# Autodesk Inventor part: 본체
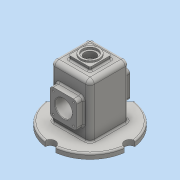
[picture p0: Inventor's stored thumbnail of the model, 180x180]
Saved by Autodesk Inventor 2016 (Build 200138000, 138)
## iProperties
Created: 2018-07
Part Number: 본체
Material: 일반
Document SubType Name: Modeling
Designer: 2-
Density: 1 g/cm^3
Appearance: 기본값
Author: 2-
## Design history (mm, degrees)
sketch "스케치1"
  geometry: C1 r 75 at (0, 0); 1 further point
  constraints: 1 centre point, 1 coincident
  dimensions: "d0" = 150 diameter of C1
extrude "돌출1" new body sketch "스케치1" distance "d1" = 10; taper "d2" = 0 deg
sketch "스케치2"
  geometry: L1 (0, 0)-(75, 0); C1 r 10 at (75, 0); 1 further point
  constraints: 2 end point, 1 centre point, 1 coincident, 1 horizontal, 1 horizontal alignment, 1 other
  dimensions: "d3" = 20 diameter of C1
extrude "돌출2" cut sketch "스케치2" distance "d4" = 10; taper "d5" = 0 deg
sketch "스케치3"
  geometry: L1 (-37, -37)-(37, -37); L2 (37, -37)-(37, 37); L3 (37, 37)-(-37, 37); L4 (-37, 37)-(-37, -37); L5 (-37, -37)-(37, 37); L6 (37, -37)-(-37, 37); 1 further point
  constraints: 12 end point, 2 midpoint, 2 parallel, 1 horizontal, 1 perpendicular
  dimensions: "d9" = 74 distance of L3.end L2.end; "d10" = 74 distance of L2.end L1.end
extrude "돌출3" join sketch "스케치3" distance "d11" = 100; taper "d12" = 0 deg
sketch "스케치4"
  geometry: L1 (20, -20)-(-20, -20); L2 (-20, -20)-(-20, 20); L3 (-20, 20)-(20, 20); L4 (20, 20)-(20, -20); L5 (20, -20)-(-20, 20); L6 (-20, -20)-(20, 20); 1 further point
  constraints: 12 end point, 2 midpoint, 2 parallel, 1 horizontal, 1 perpendicular
  dimensions: "d13" = 40 distance of L2.end L3.end; "d14" = 40 distance of L1.end L2.end
extrude "돌출4" join sketch "스케치4" distance "d15" = 7; taper "d16" = 0 deg
sketch "스케치5"
  geometry: C1 r 17.5 at (0, 0); 1 further point
  constraints: 1 centre point, 1 coincident
  dimensions: "d17" = 35 diameter of C1
extrude "돌출5" join sketch "스케치5" distance "d18" = 3; taper "d19" = 0 deg
sketch "스케치6"
  geometry: L1 (32, 32)-(-32, 32); L2 (-32, 32)-(-32, -32); L3 (-32, -32)-(32, -32); L4 (32, -32)-(32, 32); L5 (32, 32)-(-32, -32); L6 (-32, 32)-(32, -32); 1 further point
  constraints: 12 end point, 2 midpoint, 2 parallel, 1 horizontal, 1 perpendicular
  dimensions: "d20" = 64 distance of L3.end L2.end; "d21" = 64 distance of L2.end L1.end
extrude "돌출6" cut sketch "스케치6" distance "d22" = 105; taper "d23" = 0 deg
sketch "스케치7"
  geometry: L1 (37, -10)-(37, 45); L2 (12, 20)-(62, 20); L3 (62, 20)-(62, 70); L4 (62, 70)-(12, 70); L5 (12, 70)-(12, 20); L6 (12, 20)-(62, 70); L7 (62, 20)-(12, 70)
  constraints: 14 end point, 2 midpoint, 2 parallel, 1 horizontal, 1 perpendicular, 1 vertical
  dimensions: "d24" = 55 distance of L1.start L1.end; "d25" = 50 distance of L4.end L3.end; "d26" = 50 distance of L3.end L2.end
extrude "돌출7" join sketch "스케치7" distance "d27" = 13; taper "d28" = 0 deg
sketch "스케치8"
  geometry: L1 (-50, 80)-(-50, 30) reference; L2 (-50, 55)-(50, 55); L3 (50, 80)-(50, 30) reference; L4 (-37, 80)-(-50, 80) reference; L5 (-32, 0)-(-32, 105) reference; L6 (-32, 80)-(-25, 77.452); L7 (-32, 80)-(-24.551, 80); L8 (-25, 77.452)-(-25, 55); L9 (-32, 80)-(-32, 55); 1 further point
  constraints: 10 end point, 4 point on line, 2 midpoint, 1 equal length, 1 horizontal, 1 perpendicular
  dimensions: "d30" = 7 horizontal distance of L6.end L6.start; "d31" = 110 deg angle of L5 L6; "d32" = 50 diameter of L6.start L2
revolve "회전1" sketch "스케치8" stored, may be unused: angle "d33" = 90 deg
sketch "스케치9"
  geometry: C1 r 25 at (37, 45) reference; C2 r 16 at (37, 45); 1 further point
  constraints: 1 centre point, 1 coincident
  dimensions: "d34" = 32 diameter of C2
extrude "돌출8" cut sketch "스케치9" distance "d35" = 100; taper "d36" = 0 deg
fillet "모깎기1" dims "d37" = 6
sketch "스케치10"
  geometry: A1 r 6 centre (18, 64) between (18, 70) and (12, 64) reference; A2 r 6 centre (56, 64) between (62, 64) and (56, 70) reference; A3 r 6 centre (56, 26) between (56, 20) and (62, 26) reference; A4 r 6 centre (18, 26) between (12, 26) and (18, 20) reference; 5 further points
  constraints: 4 coincident
hole "구멍1" sketch "스케치10" at (18, 64), (56, 64), (56, 26), (18, 26) diameter "d38" = 3.242; stored, may be unused: countersink angle "d42" = 90 deg, drill point angle "d44" = 118 deg; dims "d39" = 8, "d40" = 4, "d41" = 2, "d43" = 10
sketch "스케치11"
  geometry: C1 r 1.621 at (38, 6) reference; A1 r 6 centre (0, 6) between (-6, 6) and (0, 0) reference; A2 r 6 centre (0, 44) between (0, 50) and (-6, 44) reference; A3 r 6 centre (38, 44) between (44, 44) and (38, 50) reference; 5 further points
  constraints: 4 coincident
hole "구멍2" sketch "스케치11" at (38, 6), (0, 6), (0, 44), (38, 44) diameter "d45" = 3.242; stored, may be unused: countersink angle "d49" = 90 deg, drill point angle "d51" = 118 deg; dims "d46" = 8, "d47" = 4, "d48" = 2, "d50" = 10
sketch "스케치12"
  geometry: 2 further points
  constraints: 1 coincident
hole "구멍3" sketch "스케치12" at (0, 0) diameter "d52" = 21; stored, may be unused: countersink angle "d56" = 90 deg, drill point angle "d58" = 118 deg; dims "d53" = 8, "d54" = 28, "d55" = 4, "d57" = 10
fillet "모깎기2" dims "d59" = 8
fillet "모깎기3" dims "d60" = 3
fillet "모깎기4" dims "d61" = 3
fillet "모깎기5" dims "d62" = 3
chamfer "모따기1" distance "d63" = 1; stored, may be unused: second distance "d64" = 2, angle "d65" = 45 deg
chamfer "모따기2" distance "d66" = 1; stored, may be unused: second distance "d67" = 2, angle "d68" = 45 deg
sketch "스케치13"
  geometry: L1 (52.277, 3.19)-(5.723, 3.19); L2 (5.723, 3.19)-(5.723, 20.81); L3 (5.723, 20.81)-(52.277, 20.81); L4 (52.277, 20.81)-(52.277, 3.19); L5 (52.277, 12)-(5.723, 12); L6 (29, 3.19)-(29, 20.81); L7 (11.5, -18)-(46.5, -18) reference; L8 (-8, 89)-(-8, 0) reference; 1 further point
  constraints: 4 end point, 4 midpoint, 2 other
  dimensions: "d69" = 30 distance between parallel lines of L7 L5; "d70" = 37 distance between parallel lines of L8 L6
feature "엠보싱1" sketch "스케치13" dims "d2" = 0, "d71" = 0.5, "d72" = 0
node "솔리드1"
pattern_circular "원형 패턴1" dims angle "d7" = 360 deg
mirror "대칭1"
mirror "대칭2"
